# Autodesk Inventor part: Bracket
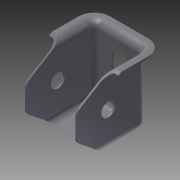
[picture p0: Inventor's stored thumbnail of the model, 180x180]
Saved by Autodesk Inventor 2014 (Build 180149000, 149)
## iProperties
Created: 2004-07
Part Number: Bracket
Document SubType Name: Modeling
Designer: leeha
Manufacturer: Standard
Standards Organization: Custom
Material: Steel, High Strength Low Alloy
Density: 7.84 g/cm^3
Mass: 269.818 g
Surface Area: 358.652 cm^2
Volume: 34.4156 cm^3
Appearance: Metal-Steel (Polished)
Author: Autodesk, Inc.
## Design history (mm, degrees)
sketch "Sketch1"
  geometry: L1 (-15.647, 19.059)-(44.353, 19.059); L2 (44.353, 19.059)-(44.353, -60.941); L3 (44.353, -60.941)-(-15.647, -60.941); L4 (-15.647, -60.941)-(-15.647, 19.059)
  constraints: 8 end point, 2 parallel, 1 horizontal, 1 perpendicular
  dimensions: "d0" = 60 distance of L1.start L1.end; "d1" = 80 distance of L3.end L1.start
extrude "Extrusion1" new body sketch "Sketch1" distance "d2" = 80; taper "d3" = 0 deg
shell "Shell1" dims "Shell_Thickness" = 2
fillet "Fillet1" dims "d5" = 6
fillet "Fillet2" dims "d6" = 8 (= d5 + Shell_Thickness)
sketch "Sketch2"
  geometry: L1 (-15.647, -60.941)-(-15.647, 11.059) reference; L2 (-13.647, -60.941)-(-13.647, 11.059) reference; L3 (-7.647, 17.059)-(36.353, 17.059) reference; L4 (42.353, 11.059)-(42.353, -60.941) reference; L5 (44.353, 11.059)-(44.353, -60.941) reference; L6 (-7.647, 19.059)-(36.353, 19.059) reference; L7 (54.353, -60.941)-(54.353, 11.059); L8 (36.353, 29.059)-(-7.647, 29.059); L9 (-25.647, 11.059)-(-25.647, -60.941); L10 (42.353, -60.941)-(54.353, -60.941); L11 (-13.647, -60.941)-(-25.647, -60.941); A1 r 6 centre (-7.647, 11.059) between (-7.647, 17.059) and (-13.647, 11.059) reference; A2 r 6 centre (36.353, 11.059) between (42.353, 11.059) and (36.353, 17.059) reference; A3 r 18 centre (-7.647, 11.059) between (-7.647, 29.059) and (-25.647, 11.059); A4 r 18 centre (36.353, 11.059) between (54.353, 11.059) and (36.353, 29.059)
  constraints: 10 end point, 4 point on circle, 4 tangent, 2 centre point, 2 perpendicular, 1 equal radius, 1 parallel
  dimensions: "d7" = 18 radius of A3 (= d6 + d8); "d8" = 10 distance between parallel lines of L8 L6; "d9" = 10 distance between parallel lines of L9 L1 (= d8); "d10" = 10 distance between parallel lines of L7 L5 (= d8)
extrude "Extrusion2" join sketch "Sketch2" distance "d11" = 2 (= Shell_Thickness); taper "d12" = 0 deg
fillet "Fillet3" dims "d13" = 6 (= d5)
fillet "Fillet4" dims "d14" = 8 (= d6)
sketch "Sketch3"
  geometry: L1 (-64, 0)-(-64, 72) reference; L2 (0, 0)-(-64, 0) reference; C1 r 8 at (-32, 36)
  constraints: 1 centre point
  dimensions: "d15" = 32 distance from line of C1.centre L1; "d16" = 16 diameter of C1; "d17" = 36 distance from line of L2 C1.centre
extrude "Extrusion3" cut sketch "Sketch3" taper "d19" = 0 deg; stored distance "d36" = 2 (= Shell_Thickness)
sketch "Sketch4"
  geometry: L1 (0, 0)-(-64, 0) reference; L2 (-64, 72)-(0, 72) reference; L3 (-97, 82)-(-47.383, 0.344); L4 (-17.955, -1.567)-(33, 62); L5 (33, 62)-(33, -24); L6 (33, -24)-(-97, -24); L7 (-97, -24)-(-97, 82); C1 r 8 at (-32, 36) reference; A1 r 18 centre (-32, 9.691) between (-47.383, 0.344) and (-17.955, -1.567); 1 further point
  constraints: 10 end point, 3 perpendicular, 2 point on circle, 2 tangent, 2 vertical alignment, 1 centre point, 1 midpoint
  dimensions: "d20" = 18 radius of A1; "d21" = 24 distance between parallel lines of L6 L1; "d22" = 86 distance of L4.end L5.end; "d23" = 106 distance of L6.end L3.start; "d24" = 70 deg angle of L4 L3; "d25" = 130 distance of L5.end L6.end
extrude "Extrusion4" cut sketch "Sketch4" stored distance "d26" = 2 (= Shell_Thickness); taper "d27" = 0 deg
fillet "Fillet5" dims "d28" = 8
sketch "Sketch5"
  geometry: L1 (44, 0)-(44, -64) reference; L2 (0, 0)-(44, 0) reference; L3 (0, -64)-(0, 0) reference; L4 (14, -14)-(14, -50); L5 (30, -14)-(30, -50); A1 r 8 centre (22, -14) between (30, -14) and (14, -14); A2 r 8 centre (22, -50) between (14, -50) and (30, -50); 3 further points
  constraints: 6 point on circle, 4 end point, 3 midpoint, 3 tangent, 2 centre point, 2 parallel, 2 point on line, 1 equal radius, 1 horizontal alignment, 1 vertical alignment
  dimensions: "d29" = 8 radius of A1; "d30" = 36 distance of A2.centre A1.centre
extrude "Extrusion5" cut sketch "Sketch5" stored distance "d31" = 2 (= Shell_Thickness); taper "d32" = 0 deg
sketch "Sketch6"
  geometry: L1 (0, 0)-(0, 64) reference; C1 r 14 at (22, 32); A1 r 8 centre (22, 50) between (30, 50) and (14, 50) reference; 1 further point
  constraints: 1 centre point, 1 horizontal alignment, 1 midpoint, 1 vertical alignment
  dimensions: "d33" = 28 diameter of C1
split "Split1" sketch "Sketch6"
node "Load Point (100 N)"
body "Solid1"
workplane "Work Plane1"
workaxis "Work Axis1"
